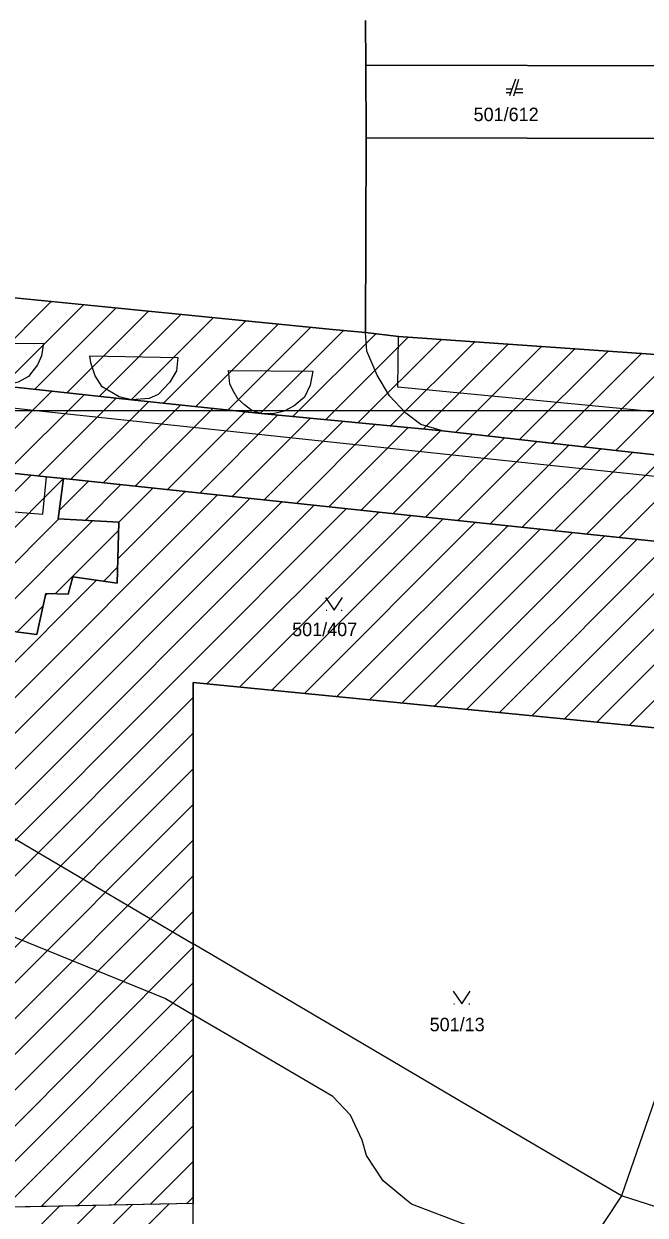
# Model space of a CAD drawing. Extents: x -264309 to -263505, y -1242443 to -1241763.
# Drawn here: x -263786.7 to -263712.8, y -1242146.2 to -1242004.6 of the extents above; entities that cross this region are included whole.
import ezdxf

# ---------------------------------------------------------------- set-up
doc = ezdxf.new("R2010")
doc.units = 0
for name, color, linetype in [('KN_2019_08_16_KLADPAR', 7, 'Continuous'), ('KN_2019_08_16_ZAPPAR', 7, 'Continuous'), ('RAM_NA_TLAC_10xA4_1-500', 7, 'Continuous'), ('SRAFY_PARCELY', 7, 'Continuous')]:
    doc.layers.add(name, color=color, linetype=linetype)

msp = doc.modelspace()

# ---------------------------------------------------------------- linework, layer by layer
at = {"layer": 'KN_2019_08_16_KLADPAR'}
for p, q in [((-263746.09, -1242004.16), (-263746.07, -1242009.46)), ((-263746.07, -1242009.46), (-263746.03, -1242018.11)), ((-263728.69, -1242012.32), (-263729.37, -1242012.32)), ((-263728.27, -1242011.12), (-263728.97, -1242013.12)), ((-263728.47, -1242013.12), (-263727.87, -1242011.12)), ((-263727.37, -1242012.32), (-263728.23, -1242012.32)), ((-263729.37, -1242012.72), (-263728.83, -1242012.72)), ((-263728.35, -1242012.72), (-263727.37, -1242012.72)), ((-263746.03, -1242018.11), (-263746.1, -1242041.26)), ((-263750.04, -1242040.89), (-263829.96, -1242032.95)), ((-263746.1, -1242041.26), (-263750.04, -1242040.89)), ((-263750.79, -1242074.29), (-263750.69, -1242074.29)), ((-263748.99, -1242074.29), (-263748.89, -1242074.29)), ((-263735.61, -1242121.1), (-263735.51, -1242121.1)), ((-263733.81, -1242121.1), (-263733.71, -1242121.1))]:
    msp.add_line(p, q, dxfattribs=at)
for points in [[(-263707.47, -1241991.99), (-263664.79, -1241992.08), (-263667.36, -1242000.21), (-263681.58, -1242045.97), (-263742.18, -1242041.73), (-263746.1, -1242041.26), (-263746.03, -1242018.11), (-263707.74, -1242018.19), (-263707.65, -1242009.54)], [(-263746.07, -1242009.46), (-263707.65, -1242009.54), (-263707.74, -1242018.19), (-263746.03, -1242018.11)], [(-263793.14, -1242057.44), (-263791.13, -1242057.66), (-263784.04, -1242058.41), (-263782.02, -1242058.63), (-263782.64, -1242063.41), (-263775.43, -1242063.83), (-263775.63, -1242071.05), (-263780.92, -1242070.3), (-263781.45, -1242072.38), (-263784.12, -1242072.3), (-263785.17, -1242077.19), (-263801.28, -1242075.1), (-263799.68, -1242061.72), (-263793.59, -1242062.32)], [(-263766.58, -1242082.89), (-263701.19, -1242089.29), (-263698.34, -1242093.87), (-263688.51, -1242109.63), (-263692.31, -1242120.01), (-263699.84, -1242134.09), (-263703.22, -1242140.34), (-263706.87, -1242146.12), (-263713.18, -1242156.13), (-263748.89, -1242212.77), (-263757.19, -1242207.25), (-263758.42, -1242206.43), (-263766.58, -1242201.01), (-263766.58, -1242144.85), (-263766.58, -1242122.39), (-263766.58, -1242113.95), (-263766.58, -1242093.5)]]:
    msp.add_lwpolyline(points, close=True, dxfattribs=at)
for points in [[(-263707.47, -1241991.99), (-263707.65, -1242009.54), (-263746.07, -1242009.46), (-263746.09, -1242004.16)], [(-263829.96, -1242032.95), (-263750.04, -1242040.89), (-263746.1, -1242041.26), (-263742.18, -1242041.73), (-263681.58, -1242045.97), (-263684.63, -1242053.31), (-263685.32, -1242054.97), (-263689.17, -1242055.8), (-263695.33, -1242056.9), (-263699.55, -1242057.11), (-263715.96, -1242055.32), (-263736.94, -1242052.97), (-263758.51, -1242050.91), (-263773.94, -1242049.27), (-263789.68, -1242047.57)], [(-263789.68, -1242047.57), (-263773.94, -1242049.27), (-263758.51, -1242050.91), (-263736.94, -1242052.97), (-263715.96, -1242055.32), (-263699.55, -1242057.11), (-263695.33, -1242056.9), (-263689.17, -1242055.8), (-263685.32, -1242054.97), (-263686.23, -1242058.02), (-263688.36, -1242065.12), (-263689.5, -1242068.4), (-263736.68, -1242063.45), (-263782.02, -1242058.63), (-263784.04, -1242058.41), (-263791.13, -1242057.66)], [(-263801.28, -1242075.1), (-263785.17, -1242077.19), (-263784.12, -1242072.3), (-263781.45, -1242072.38), (-263780.92, -1242070.3), (-263775.63, -1242071.05), (-263775.43, -1242063.83), (-263782.64, -1242063.41), (-263782.02, -1242058.63), (-263736.68, -1242063.45), (-263689.5, -1242068.4), (-263696.42, -1242088.33), (-263698.34, -1242093.87), (-263701.19, -1242089.29), (-263766.58, -1242082.89), (-263766.58, -1242093.5), (-263766.58, -1242113.95), (-263766.58, -1242122.39), (-263766.58, -1242144.85), (-263804.58, -1242145.58)], [(-263750.84, -1242072.79), (-263749.84, -1242074.29), (-263748.84, -1242072.79)], [(-263735.66, -1242119.6), (-263734.66, -1242121.1), (-263733.66, -1242119.6)]]:
    msp.add_lwpolyline(points, dxfattribs=at)
at = {"layer": 'KN_2019_08_16_ZAPPAR'}
for p, q in [((-263742.26, -1242047.78), (-263742.18, -1242041.73)), ((-263794.51, -1242042.59), (-263784.38, -1242042.55)), ((-263837.1, -1242044.85), (-263784.51, -1242050.62)), ((-263778.87, -1242044.03), (-263768.41, -1242044.24)), ((-263762.4, -1242045.79), (-263752.37, -1242045.85)), ((-263743.26, -1242048.79), (-263744.71, -1242046.35)), ((-263684.63, -1242053.31), (-263742.26, -1242047.78)), ((-263784.47, -1242062.88), (-263784.04, -1242058.41)), ((-263791.54, -1242062.3), (-263784.47, -1242062.88)), ((-263808.5, -1242089.28), (-263779.5, -1242106.34)), ((-263779.5, -1242106.34), (-263766.58, -1242113.95)), ((-263735.97, -1242131.99), (-263766.58, -1242113.95)), ((-263759.67, -1242126.44), (-263766.58, -1242122.39)), ((-263749.97, -1242132.12), (-263759.67, -1242126.44)), ((-263715.64, -1242143.92), (-263735.97, -1242131.99))]:
    msp.add_line(p, q, dxfattribs=at)
for points in [[(-263744.71, -1242046.35), (-263745.94, -1242043.47), (-263746.1, -1242041.26)], [(-263784.38, -1242042.55), (-263784.64, -1242044.03), (-263785.09, -1242045.11), (-263786.18, -1242046.49), (-263787.4, -1242047.18), (-263788.56, -1242047.44), (-263789.68, -1242047.57)], [(-263778.26, -1242046.43), (-263778.77, -1242044.88), (-263778.87, -1242044.03)], [(-263768.41, -1242044.24), (-263768.58, -1242045.81), (-263769.36, -1242047.18), (-263770.75, -1242048.64), (-263771.82, -1242049.12), (-263773.94, -1242049.27), (-263775.39, -1242048.93), (-263777.41, -1242047.71), (-263778.26, -1242046.43)], [(-263758.51, -1242050.91), (-263759.19, -1242050.69), (-263759.77, -1242050.41), (-263760.49, -1242049.88), (-263761.28, -1242049.16), (-263761.87, -1242048.13), (-263762.22, -1242047.36), (-263762.4, -1242045.79)], [(-263752.37, -1242045.85), (-263752.68, -1242047.51), (-263753.35, -1242048.96), (-263754.58, -1242049.99), (-263755.75, -1242050.63), (-263757.07, -1242050.94), (-263758.51, -1242050.91)], [(-263736.94, -1242052.97), (-263739.52, -1242052.22), (-263741.32, -1242050.85), (-263743.26, -1242048.79)], [(-263784.51, -1242050.62), (-263726.8, -1242056.75), (-263699.93, -1242059.57), (-263693.82, -1242059.4), (-263689.88, -1242058.88), (-263687.3, -1242058.33), (-263686.23, -1242058.02)], [(-263698.34, -1242093.87), (-263715.64, -1242143.92), (-263719.68, -1242150.03), (-263738.33, -1242178.96)], [(-263790.88, -1242114.27), (-263789.91, -1242112.35), (-263769.87, -1242120.46), (-263766.58, -1242122.39)], [(-263713.18, -1242156.13), (-263717.55, -1242151.26), (-263719.68, -1242150.03), (-263721.39, -1242149.06), (-263723.21, -1242148.44), (-263725.82, -1242148.54), (-263727.71, -1242149.84), (-263740.62, -1242144.92), (-263741.22, -1242144.43), (-263743.99, -1242142.15), (-263745.98, -1242139.12), (-263746.48, -1242137.32), (-263747.89, -1242134.32), (-263749.97, -1242132.12)], [(-263706.87, -1242146.12), (-263708.6, -1242146.2), (-263715.64, -1242143.92)]]:
    msp.add_lwpolyline(points, dxfattribs=at)
at = {"layer": 'RAM_NA_TLAC_10xA4_1-500'}
msp.add_lwpolyline([(-264210.83, -1242050.54), (-264105.83, -1242050.54), (-264000.83, -1242050.54), (-263895.83, -1242050.54), (-263790.83, -1242050.54), (-263685.83, -1242050.54), (-263685.83, -1242199.04), (-263685.83, -1242347.54), (-263790.83, -1242347.54), (-263895.83, -1242347.54), (-264000.83, -1242347.54), (-264105.83, -1242347.54), (-264210.83, -1242347.54), (-264210.83, -1242199.04)], close=True, dxfattribs=at)
at = {"layer": 'SRAFY_PARCELY'}
for p, q in [((-263793.15, -1242047.25), (-263783.47, -1242037.57)), ((-263789.27, -1242047.61), (-263779.61, -1242037.95)), ((-263785.44, -1242048.03), (-263775.75, -1242038.34)), ((-263781.61, -1242048.44), (-263771.89, -1242038.72)), ((-263777.78, -1242048.86), (-263768.03, -1242039.1)), ((-263773.95, -1242049.27), (-263764.17, -1242039.49)), ((-263770.12, -1242049.68), (-263760.31, -1242039.87)), ((-263766.28, -1242050.08), (-263756.45, -1242040.25)), ((-263762.45, -1242050.49), (-263752.59, -1242040.64)), ((-263758.61, -1242050.9), (-263748.73, -1242041.01)), ((-263754.74, -1242051.27), (-263744.88, -1242041.41)), ((-263750.87, -1242051.64), (-263741.04, -1242041.81)), ((-263746.99, -1242052.01), (-263737.07, -1242042.09)), ((-263743.12, -1242052.38), (-263733.11, -1242042.36)), ((-263739.25, -1242052.75), (-263729.14, -1242042.64)), ((-263735.4, -1242053.14), (-263725.18, -1242042.92)), ((-263731.58, -1242053.57), (-263721.21, -1242043.2)), ((-263727.77, -1242054), (-263717.25, -1242043.47)), ((-263723.95, -1242054.42), (-263713.28, -1242043.75)), ((-263720.14, -1242054.85), (-263709.32, -1242044.03)), ((-263716.32, -1242055.28), (-263705.35, -1242044.31)), ((-263792.65, -1242057.49), (-263783.4, -1242048.25)), ((-263788.82, -1242057.9), (-263779.57, -1242048.66)), ((-263784.98, -1242058.31), (-263775.74, -1242049.08)), ((-263781.15, -1242058.72), (-263771.91, -1242049.49)), ((-263777.31, -1242059.13), (-263768.08, -1242049.89)), ((-263773.48, -1242059.54), (-263764.24, -1242050.3)), ((-263769.64, -1242059.95), (-263760.41, -1242050.71)), ((-263765.81, -1242060.35), (-263756.55, -1242051.1)), ((-263761.97, -1242060.76), (-263752.68, -1242051.47)), ((-263758.14, -1242061.17), (-263748.81, -1242051.84)), ((-263754.3, -1242061.58), (-263744.93, -1242052.21)), ((-263750.47, -1242061.98), (-263741.06, -1242052.58)), ((-263746.63, -1242062.39), (-263737.19, -1242052.95)), ((-263742.8, -1242062.8), (-263733.37, -1242053.37)), ((-263738.96, -1242063.21), (-263729.55, -1242053.8)), ((-263735.13, -1242063.61), (-263725.74, -1242054.22)), ((-263731.29, -1242064.02), (-263721.92, -1242054.65)), ((-263727.45, -1242064.42), (-263718.11, -1242055.08)), ((-263723.61, -1242064.82), (-263714.29, -1242055.5)), ((-263719.77, -1242065.22), (-263710.46, -1242055.92)), ((-263715.93, -1242065.63), (-263706.64, -1242056.34)), ((-263801.08, -1242073.46), (-263785.84, -1242058.22)), ((-263798.8, -1242075.42), (-263782.02, -1242058.64)), ((-263782.51, -1242062.42), (-263779.04, -1242058.95)), ((-263845.24, -1242142.12), (-263763.7, -1242060.58)), ((-263779.44, -1242063.6), (-263775.2, -1242059.35)), ((-263775.55, -1242068.19), (-263767.53, -1242060.17)), ((-263775.43, -1242063.83), (-263771.37, -1242059.76)), ((-263844.47, -1242145.59), (-263759.86, -1242060.99)), ((-263840.85, -1242146.22), (-263756.03, -1242061.39)), ((-263836.6, -1242146.2), (-263752.19, -1242061.8)), ((-263832.27, -1242146.12), (-263748.36, -1242062.21)), ((-263795.05, -1242075.91), (-263782.55, -1242063.41)), ((-263764.96, -1242083.05), (-263744.52, -1242062.62)), ((-263761.09, -1242083.43), (-263740.69, -1242063.02)), ((-263757.23, -1242083.81), (-263736.85, -1242063.43)), ((-263791.29, -1242076.4), (-263778.55, -1242063.65)), ((-263782.99, -1242072.33), (-263775.46, -1242064.8)), ((-263753.36, -1242084.18), (-263733.01, -1242063.83)), ((-263749.5, -1242084.56), (-263729.17, -1242064.24)), ((-263745.63, -1242084.94), (-263725.33, -1242064.64)), ((-263741.77, -1242085.32), (-263721.49, -1242065.04)), ((-263737.9, -1242085.7), (-263717.65, -1242065.45)), ((-263734.04, -1242086.07), (-263713.81, -1242065.85)), ((-263730.18, -1242086.45), (-263709.97, -1242066.25)), ((-263726.31, -1242086.83), (-263706.13, -1242066.65)), ((-263722.45, -1242087.21), (-263702.3, -1242067.06)), ((-263718.58, -1242087.59), (-263698.46, -1242067.46)), ((-263714.72, -1242087.97), (-263694.62, -1242067.86)), ((-263777.23, -1242070.82), (-263775.58, -1242069.17)), ((-263845.33, -1242137.97), (-263778.07, -1242070.7)), ((-263784.18, -1242072.57), (-263783.91, -1242072.31)), ((-263787.54, -1242076.88), (-263784.44, -1242073.78)), ((-263827.94, -1242146.04), (-263766.58, -1242084.67)), ((-263823.62, -1242145.95), (-263766.58, -1242088.92)), ((-263819.29, -1242145.87), (-263766.58, -1242093.16)), ((-263814.96, -1242145.78), (-263766.58, -1242097.4)), ((-263810.63, -1242145.7), (-263766.58, -1242101.64)), ((-263806.31, -1242145.61), (-263766.58, -1242105.89)), ((-263801.98, -1242145.53), (-263766.58, -1242110.13)), ((-263797.66, -1242145.45), (-263766.58, -1242114.37)), ((-263793.33, -1242145.36), (-263766.58, -1242118.61)), ((-263789, -1242145.28), (-263766.58, -1242122.86)), ((-263784.68, -1242145.2), (-263766.58, -1242127.1)), ((-263780.35, -1242145.11), (-263766.58, -1242131.34)), ((-263776.03, -1242145.03), (-263766.58, -1242135.59)), ((-263771.7, -1242144.95), (-263766.58, -1242139.83)), ((-263767.37, -1242144.87), (-263766.58, -1242144.07)), ((-263854.35, -1242217.02), (-263782.48, -1242145.16)), ((-263854.26, -1242221.18), (-263778.16, -1242145.07)), ((-263854.17, -1242225.33), (-263773.83, -1242144.99)), ((-263854.09, -1242229.49), (-263769.5, -1242144.91)), ((-263766.58, -1242144.85), (-263804.58, -1242145.58)), ((-263766.58, -1242201.01), (-263766.58, -1242144.85))]:
    msp.add_line(p, q, dxfattribs=at)

# ---------------------------------------------------------------- texts
at = {"layer": 'KN_2019_08_16_KLADPAR'}
for s, p in [('501/612', (-263733.24, -1242016.13)), ('501/407', (-263754.82, -1242077.37)), ('501/13', (-263738.47, -1242124.35))]:
    msp.add_text(s, height=1.6, dxfattribs=at).set_placement(p)

doc.saveas('drawing.dxf')
